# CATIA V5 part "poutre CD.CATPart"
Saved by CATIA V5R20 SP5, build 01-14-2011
Part number: poutre CD
Bounding box of the stored display mesh (mm): x 0 to 20, y 142.594 to 167.574, z 27.108 to 72.28
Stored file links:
  F:\iao fini\poutre CD.CATPart
  F:\iao fini\iao-finipbgliss.CATProduct
  F:\iao fini\poutre3.CATPart
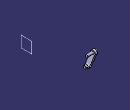
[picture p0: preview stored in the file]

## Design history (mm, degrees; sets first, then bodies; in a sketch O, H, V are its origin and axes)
Set1
  Sketch1 on Plane1, origin (0, 0, 0), H (0, 1, 0), V (0, 0, 1)
    circle A1 centre (147.483, 32.022) radius 2.902
    point P1 (147.483, 32.022)
    reference projected point E1 (147.483, 32.022) from Point1
    arc A2 centre (147.483, 32.022) radius 4.9159 from (142.9313, 33.8791) to (151.9927, 30.0652) ccw
    point P2 (147.483, 32.022)
    reference projected point E2 (147.483, 32.022) from Point1
    arc A3 centre (162.215, 66.933) radius 5.3685 from (166.7305, 64.0295) to (157.2233, 68.9088) ccw
    point P3 (162.215, 66.933)
    reference projected point E3 (162.215, 66.933) from Point2
    line L1 (166.7305, 64.0295) -> (151.9927, 30.0652)
    line L2 (157.2233, 68.9088) -> (142.9313, 33.8791)
    circle A4 centre (162.215, 66.933) radius 2.902
    point P8 (162.215, 66.933)
    reference projected point E4 (162.215, 66.933) from Point2
    radius A1 = 2.902
    radius A4 = 2.902
    coincidence: P1 E1, P2 E2, P3 E3, P8 E4
    tangency: L1 A2, L2 A2
Set2
  Plane1 "plan profil": linked copy from another document
  Point1 "D": linked copy from another document
  Point2 "C": linked copy from another document
Body1 (main body)
  Pad1: profile Sketch1, direction (1, 0, 0), length 5
  Sketch2 on Plane1, origin (0, 0, 0), H (0, 1, 0), V (0, 0, 1)
    circle A1 centre (147.483, 32.022) radius 2.902
    point P1 (147.483, 32.022)
    reference projected point E1 (147.483, 32.022) from Point1
    radius A1 = 2.902
    coincidence: P1 E1
  Pad2: profile Sketch2, direction (1, 0, 0), length 10
  Sketch3 on Plane1, origin (0, 0, 0), H (0, 1, 0), V (0, 0, 1)
    circle A1 centre (162.215, 66.933) radius 2.902
    point P1 (162.215, 66.933)
    reference projected point E1 (162.215, 66.933) from Point2
    radius A1 = 2.902
    coincidence: E1 P1
  Pad3: profile Sketch3, direction (1, 0, 0), length 20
